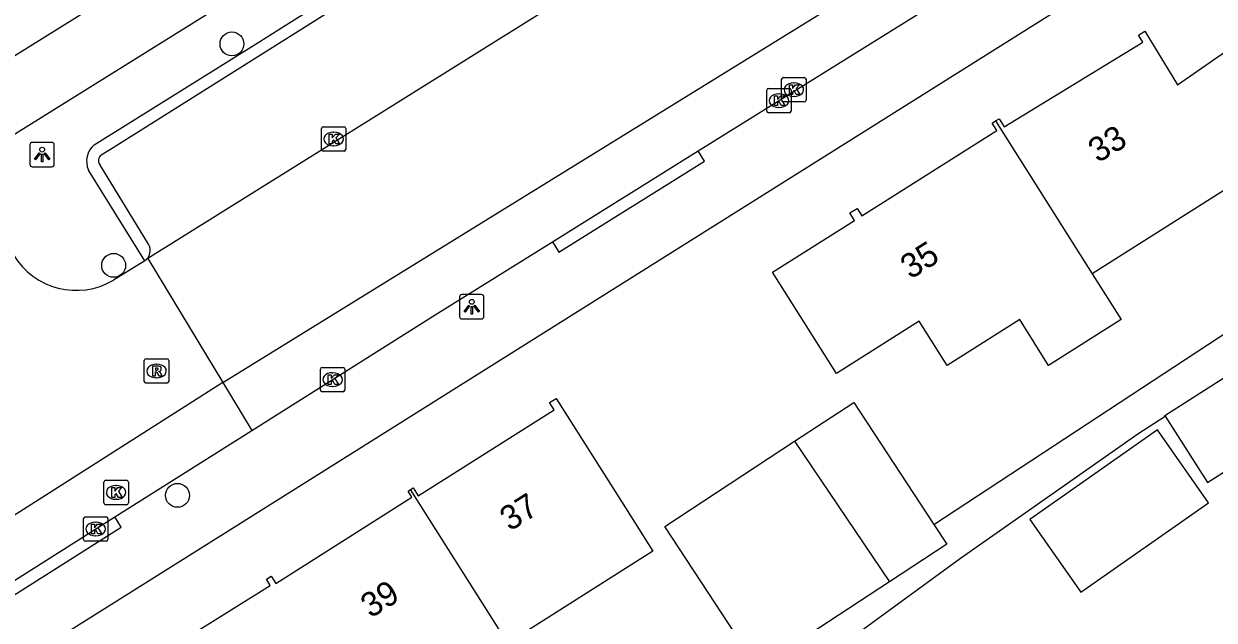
# Model space of a CAD drawing. Extents: x 159280 to 160375, y 384531 to 385872.
# Drawn here: x 159606.27 to 159655.03, y 385320.28 to 385344.69 of the extents above; entities that cross this region are included whole.
import ezdxf

# ---------------------------------------------------------------- set-up
doc = ezdxf.new("R2010")
doc.units = 0
for name, color, linetype in [('IMGEO_Boom', 7, 'Continuous'), ('IMGEO_Kolk', 7, 'Continuous'), ('IMGEO_Lichtpunt', 7, 'Continuous'), ('IMGEO_Pand', 7, 'Continuous'), ('IMGEO_Pand_nummerreeks', 7, 'Continuous'), ('IMGEO_Parkeervlak_open', 7, 'Continuous'), ('IMGEO_Rijbaan_lokaal_open', 7, 'Continuous'), ('IMGEO_Rioolput', 7, 'Continuous'), ('IMGEO_Voetpad_open', 7, 'Continuous')]:
    doc.layers.add(name, color=color, linetype=linetype)

msp = doc.modelspace()

# ---------------------------------------------------------------- linework, layer by layer
at = {"layer": 'IMGEO_Boom'}
for centre in [(159614.795, 385343.87), (159609.948, 385334.806), (159612.562, 385325.39)]:
    msp.add_circle(centre, 0.489, dxfattribs=at)
at = {"layer": 'IMGEO_Kolk'}
for p, q in [((159637.314, 385341.571), (159637.314, 385342.423)), ((159637.389, 385342.497), (159638.241, 385342.497)), ((159637.802, 385342.277), (159637.827, 385342.277)), ((159638.315, 385342.423), (159638.315, 385341.571)), ((159636.703, 385341.123), (159636.703, 385341.975)), ((159636.778, 385342.049), (159637.63, 385342.049)), ((159637.191, 385341.829), (159637.216, 385341.829)), ((159637.704, 385341.975), (159637.704, 385341.123)), ((159638.241, 385341.497), (159637.389, 385341.497)), ((159637.825, 385341.717), (159637.8, 385341.717)), ((159637.63, 385341.049), (159636.778, 385341.049)), ((159637.214, 385341.269), (159637.189, 385341.269)), ((159618.459, 385339.554), (159618.459, 385340.406)), ((159618.534, 385340.48), (159619.386, 385340.48)), ((159619.46, 385340.406), (159619.46, 385339.554)), ((159618.947, 385340.26), (159618.972, 385340.26)), ((159619.386, 385339.48), (159618.534, 385339.48)), ((159618.97, 385339.7), (159618.945, 385339.7)), ((159618.493, 385330.629), (159619.345, 385330.629)), ((159618.418, 385329.703), (159618.418, 385330.555)), ((159618.906, 385330.409), (159618.931, 385330.409)), ((159619.419, 385330.555), (159619.419, 385329.703)), ((159619.345, 385329.629), (159618.493, 385329.629)), ((159618.929, 385329.849), (159618.904, 385329.849)), ((159609.549, 385325.083), (159609.549, 385325.935)), ((159609.624, 385326.009), (159610.476, 385326.009)), ((159610.037, 385325.789), (159610.062, 385325.789)), ((159610.55, 385325.935), (159610.55, 385325.083)), ((159610.06, 385325.229), (159610.035, 385325.229)), ((159610.476, 385325.009), (159609.624, 385325.009)), ((159608.713, 385323.586), (159608.713, 385324.438)), ((159608.788, 385324.512), (159609.64, 385324.512)), ((159609.201, 385324.292), (159609.226, 385324.292)), ((159609.714, 385324.438), (159609.714, 385323.586)), ((159609.64, 385323.512), (159608.788, 385323.512)), ((159609.224, 385323.732), (159609.199, 385323.732))]:
    msp.add_line(p, q, dxfattribs=at)
for points in [[(159637.314, 385341.571), (159637.314, 385342.423)], [(159637.389, 385342.497), (159638.241, 385342.497)], [(159638.315, 385342.423), (159638.315, 385341.571)], [(159636.703, 385341.123), (159636.703, 385341.975)], [(159636.778, 385342.049), (159637.63, 385342.049)], [(159637.635, 385342.197), (159637.758, 385342.197), (159637.758, 385342.046), (159637.888, 385342.197), (159638.052, 385342.197), (159637.906, 385342.046), (159638.059, 385341.797), (159637.907, 385341.797), (159637.822, 385341.961), (159637.758, 385341.894), (159637.758, 385341.797), (159637.635, 385341.797), (159637.635, 385342.197)], [(159637.704, 385341.975), (159637.704, 385341.123)], [(159637.024, 385341.749), (159637.147, 385341.749), (159637.147, 385341.598), (159637.277, 385341.749), (159637.441, 385341.749), (159637.295, 385341.598), (159637.448, 385341.349), (159637.296, 385341.349), (159637.211, 385341.513), (159637.147, 385341.446), (159637.147, 385341.349), (159637.024, 385341.349), (159637.024, 385341.749)], [(159638.241, 385341.497), (159637.389, 385341.497)], [(159637.63, 385341.049), (159636.778, 385341.049)], [(159618.459, 385339.554), (159618.459, 385340.406)], [(159618.534, 385340.48), (159619.386, 385340.48)], [(159619.46, 385340.406), (159619.46, 385339.554)], [(159618.78, 385340.18), (159618.903, 385340.18), (159618.903, 385340.029), (159619.033, 385340.18), (159619.197, 385340.18), (159619.051, 385340.029), (159619.204, 385339.78), (159619.052, 385339.78), (159618.967, 385339.944), (159618.903, 385339.877), (159618.903, 385339.78), (159618.78, 385339.78), (159618.78, 385340.18)], [(159619.386, 385339.48), (159618.534, 385339.48)], [(159618.493, 385330.629), (159619.345, 385330.629)], [(159618.418, 385329.703), (159618.418, 385330.555)], [(159618.739, 385330.329), (159618.862, 385330.329), (159618.862, 385330.178), (159618.992, 385330.329), (159619.156, 385330.329), (159619.01, 385330.178), (159619.163, 385329.929), (159619.011, 385329.929), (159618.926, 385330.093), (159618.862, 385330.026), (159618.862, 385329.929), (159618.739, 385329.929), (159618.739, 385330.329)], [(159619.419, 385330.555), (159619.419, 385329.703)], [(159619.345, 385329.629), (159618.493, 385329.629)], [(159609.549, 385325.083), (159609.549, 385325.935)], [(159609.624, 385326.009), (159610.476, 385326.009)], [(159609.87, 385325.709), (159609.993, 385325.709), (159609.993, 385325.558), (159610.123, 385325.709), (159610.287, 385325.709), (159610.141, 385325.558), (159610.294, 385325.309), (159610.142, 385325.309), (159610.057, 385325.473), (159609.993, 385325.406), (159609.993, 385325.309), (159609.87, 385325.309), (159609.87, 385325.709)], [(159610.55, 385325.935), (159610.55, 385325.083)], [(159610.476, 385325.009), (159609.624, 385325.009)], [(159608.713, 385323.586), (159608.713, 385324.438)], [(159608.788, 385324.512), (159609.64, 385324.512)], [(159609.714, 385324.438), (159609.714, 385323.586)], [(159609.034, 385324.212), (159609.157, 385324.212), (159609.157, 385324.061), (159609.287, 385324.212), (159609.451, 385324.212), (159609.305, 385324.061), (159609.458, 385323.812), (159609.306, 385323.812), (159609.221, 385323.976), (159609.157, 385323.909), (159609.157, 385323.812), (159609.034, 385323.812), (159609.034, 385324.212)], [(159609.64, 385323.512), (159608.788, 385323.512)]]:
    msp.add_lwpolyline(points, dxfattribs=at)
for centre, start, end in [((159637.391, 385342.421), 91.552, 178.448), ((159637.391, 385342.421), 91.552, 178.448), ((159638.239, 385342.421), 1.552, 88.448), ((159638.239, 385342.421), 1.552, 88.448), ((159636.78, 385341.973), 91.552, 178.448), ((159636.78, 385341.973), 91.552, 178.448), ((159637.628, 385341.973), 1.552, 88.448), ((159637.628, 385341.973), 1.552, 88.448), ((159637.391, 385341.573), 181.552, 268.448), ((159637.391, 385341.573), 181.552, 268.448), ((159638.239, 385341.573), 271.552, 358.448), ((159638.239, 385341.573), 271.552, 358.448), ((159636.78, 385341.125), 181.552, 268.448), ((159636.78, 385341.125), 181.552, 268.448), ((159637.628, 385341.125), 271.552, 358.448), ((159637.628, 385341.125), 271.552, 358.448), ((159618.536, 385340.404), 91.552, 178.448), ((159618.536, 385340.404), 91.552, 178.448), ((159619.384, 385340.404), 1.552, 88.448), ((159619.384, 385340.404), 1.552, 88.448), ((159618.536, 385339.556), 181.552, 268.448), ((159618.536, 385339.556), 181.552, 268.448), ((159619.384, 385339.556), 271.552, 358.448), ((159619.384, 385339.556), 271.552, 358.448), ((159618.495, 385330.553), 91.552, 178.448), ((159618.495, 385330.553), 91.552, 178.448), ((159619.343, 385330.553), 1.552, 88.448), ((159619.343, 385330.553), 1.552, 88.448), ((159618.495, 385329.705), 181.552, 268.448), ((159618.495, 385329.705), 181.552, 268.448), ((159619.343, 385329.705), 271.552, 358.448), ((159619.343, 385329.705), 271.552, 358.448), ((159609.626, 385325.933), 91.552, 178.448), ((159609.626, 385325.933), 91.552, 178.448), ((159610.474, 385325.933), 1.552, 88.448), ((159610.474, 385325.933), 1.552, 88.448), ((159609.626, 385325.085), 181.552, 268.448), ((159609.626, 385325.085), 181.552, 268.448), ((159610.474, 385325.085), 271.552, 358.448), ((159610.474, 385325.085), 271.552, 358.448), ((159608.79, 385324.436), 91.552, 178.448), ((159608.79, 385324.436), 91.552, 178.448), ((159609.638, 385324.436), 1.552, 88.448), ((159609.638, 385324.436), 1.552, 88.448), ((159608.79, 385323.588), 181.552, 268.448), ((159608.79, 385323.588), 181.552, 268.448), ((159609.638, 385323.588), 271.552, 358.448), ((159609.638, 385323.588), 271.552, 358.448)]:
    msp.add_arc(centre, 0.0765, start, end, dxfattribs=at)
for centre, major_axis, ratio, start_param, end_param in [((159637.801, 385341.997), (-0.387, 0.002), 0.722429, 4.712389, 7.853982), ((159637.826, 385341.997), (-0.39, 0.002), 0.717154, 1.570796, 4.712389), ((159637.19, 385341.549), (-0.387, 0.002), 0.722429, 4.712389, 7.853982), ((159637.215, 385341.549), (-0.39, 0.002), 0.717154, 1.570796, 4.712389), ((159618.946, 385339.98), (-0.387, 0.002), 0.722429, 4.712389, 7.853982), ((159618.971, 385339.98), (-0.39, 0.002), 0.717154, 1.570796, 4.712389), ((159618.905, 385330.129), (-0.387, 0.002), 0.722429, 4.712389, 7.853982), ((159618.93, 385330.129), (-0.39, 0.002), 0.717154, 1.570796, 4.712389), ((159610.036, 385325.509), (-0.387, 0.002), 0.722429, 4.712389, 7.853982), ((159610.061, 385325.509), (-0.39, 0.002), 0.717154, 1.570796, 4.712389), ((159609.2, 385324.012), (-0.387, 0.002), 0.722429, 4.712389, 7.853982), ((159609.225, 385324.012), (-0.39, 0.002), 0.717154, 1.570796, 4.712389)]:
    msp.add_ellipse(centre, major_axis=major_axis, ratio=ratio, start_param=start_param, end_param=end_param, dxfattribs=at)
at = {"layer": 'IMGEO_Lichtpunt'}
for p, q in [((159607.422, 385339.842), (159606.614, 385339.842)), ((159607.422, 385339.842), (159606.614, 385339.842)), ((159606.52, 385339.747), (159606.52, 385338.94)), ((159606.52, 385339.747), (159606.52, 385338.94)), ((159607.516, 385338.94), (159607.516, 385339.747)), ((159607.516, 385338.94), (159607.516, 385339.747)), ((159606.614, 385338.846), (159607.422, 385338.846)), ((159606.614, 385338.846), (159607.422, 385338.846)), ((159624.12, 385333.512), (159624.12, 385332.705)), ((159624.12, 385333.512), (159624.12, 385332.705)), ((159625.022, 385333.607), (159624.214, 385333.607)), ((159625.022, 385333.607), (159624.214, 385333.607)), ((159625.116, 385332.705), (159625.116, 385333.512)), ((159625.116, 385332.705), (159625.116, 385333.512)), ((159624.214, 385332.611), (159625.022, 385332.611)), ((159624.214, 385332.611), (159625.022, 385332.611))]:
    msp.add_line(p, q, dxfattribs=at)
for points in [[(159606.894, 385339.411), (159606.933, 385339.383), (159606.745, 385339.121), (159606.707, 385339.148), (159606.894, 385339.411)], [(159606.996, 385339.363), (159607.043, 385339.363), (159607.043, 385339.041), (159606.996, 385339.041), (159606.996, 385339.363)], [(159607.106, 385339.383), (159607.144, 385339.41), (159607.331, 385339.148), (159607.292, 385339.12), (159607.106, 385339.383)], [(159624.494, 385333.176), (159624.533, 385333.148), (159624.345, 385332.886), (159624.307, 385332.913), (159624.494, 385333.176)], [(159624.596, 385333.128), (159624.643, 385333.128), (159624.643, 385332.806), (159624.596, 385332.806), (159624.596, 385333.128)], [(159624.706, 385333.148), (159624.744, 385333.175), (159624.931, 385332.913), (159624.892, 385332.885), (159624.706, 385333.148)]]:
    msp.add_lwpolyline(points, dxfattribs=at)
for centre in [(159607.019, 385339.545), (159624.619, 385333.31)]:
    msp.add_circle(centre, 0.0994, dxfattribs=at)
for centre, start, end in [((159606.614, 385339.747), 90, 180), ((159606.614, 385339.747), 90, 180), ((159607.422, 385339.747), 0, 90), ((159607.422, 385339.747), 0, 90), ((159606.614, 385338.94), 180, 270), ((159606.614, 385338.94), 180, 270), ((159607.422, 385338.94), 270, 0), ((159607.422, 385338.94), 270, 360), ((159624.214, 385333.512), 90, 180), ((159624.214, 385333.512), 90, 180), ((159625.022, 385333.512), 0, 90), ((159625.022, 385333.512), 0, 90), ((159624.214, 385332.705), 180, 270), ((159624.214, 385332.705), 180, 270), ((159625.022, 385332.705), 270, 0), ((159625.022, 385332.705), 270, 360)]:
    msp.add_arc(centre, 0.0946, start, end, dxfattribs=at)
at = {"layer": 'IMGEO_Pand'}
for points in [[(159646.082, 385340.717), (159646.221, 385340.805), (159646.429, 385340.476), (159652.114, 385343.937), (159651.933, 385344.227), (159652.197, 385344.395), (159653.532, 385342.202), (159658.982, 385345.989)], [(159650.038, 385334.462), (159651.222, 385332.59), (159648.251, 385330.711), (159647.067, 385332.583), (159644.102, 385330.707), (159642.95, 385332.526), (159639.561, 385330.382), (159636.943, 385334.522), (159640.303, 385336.648), (159640.11, 385336.952), (159640.402, 385337.137), (159640.596, 385336.829), (159646.132, 385340.331), (159645.943, 385340.629), (159646.082, 385340.717)], [(159646.082, 385340.717), (159650.038, 385334.462)], [(159661.483, 385335.963), (159659.249, 385339.358), (159659.069, 385339.617), (159656.4, 385337.862), (159656.095, 385338.294), (159650.038, 385334.462)], [(159653.032, 385328.628), (159653.008, 385328.666), (159656.411, 385330.831), (159656.611, 385330.517)], [(159653.032, 385328.628), (159654.758, 385325.916), (159658.16, 385328.081), (159656.611, 385330.517)], [(159622.11, 385325.63), (159622.217, 385325.697), (159622.424, 385325.371), (159627.993, 385328.898), (159627.807, 385329.191), (159628.074, 385329.359), (159630.749, 385325.135), (159632.036, 385323.102), (159626.095, 385319.34)], [(159637.838, 385327.602), (159640.269, 385329.197), (159643.552, 385324.195)], [(159649.577, 385321.426), (159654.797, 385325.087), (159652.707, 385328.066), (159647.488, 385324.405), (159649.577, 385321.426)], [(159636.344, 385318.32), (159632.535, 385324.122), (159637.838, 385327.602)], [(159637.838, 385327.602), (159641.726, 385321.852)], [(159616.768, 385313.509), (159614.943, 385316.406), (159612.948, 385319.573), (159616.365, 385321.706), (159616.206, 385321.957), (159616.398, 385322.079), (159616.587, 385321.781), (159622.166, 385325.314), (159622.007, 385325.565), (159622.11, 385325.63)], [(159626.095, 385319.34), (159622.11, 385325.63)], [(159643.552, 385324.195), (159644.077, 385323.395), (159641.726, 385321.852)], [(159641.726, 385321.852), (159636.344, 385318.32)]]:
    msp.add_lwpolyline(points, dxfattribs=at)
at = {"layer": 'IMGEO_Parkeervlak_open'}
msp.add_lwpolyline([(159614.419, 385330.007), (159615.607, 385328.042)], dxfattribs=at)
at = {"layer": 'IMGEO_Rijbaan_lokaal_open'}
for points in [[(159614.419, 385330.007), (159640.215, 385345.938), (159644.265, 385348.476), (159693.538, 385379.269), (159694.578, 385379.919), (159695.635, 385378.201)], [(159627.402, 385345.101), (159618.688, 385339.659), (159611.352, 385335.08)], [(159611.219, 385334.995), (159609.941, 385334.203)], [(159611.352, 385335.08), (159611.219, 385334.995)], [(159611.352, 385335.08), (159614.419, 385330.007)], [(159614.419, 385330.007), (159588.255, 385313.356)]]:
    msp.add_lwpolyline(points, dxfattribs=at)
msp.add_arc((159608.412, 385336.771), 2.989, 210.8156, 300.7699, dxfattribs=at)
at = {"layer": 'IMGEO_Rioolput'}
for p, q in [((159611.204, 385330.056), (159611.204, 385330.908)), ((159611.279, 385330.982), (159612.131, 385330.982)), ((159611.692, 385330.762), (159611.717, 385330.762)), ((159612.205, 385330.908), (159612.205, 385330.056)), ((159611.715, 385330.202), (159611.69, 385330.202)), ((159612.131, 385329.982), (159611.279, 385329.982))]:
    msp.add_line(p, q, dxfattribs=at)
for points in [[(159611.204, 385330.056), (159611.204, 385330.908)], [(159611.279, 385330.982), (159612.131, 385330.982)], [(159611.793, 385330.68), (159611.541, 385330.682), (159611.541, 385330.282)], [(159611.719, 385330.601), (159611.665, 385330.601), (159611.665, 385330.52)], [(159612.205, 385330.908), (159612.205, 385330.056)], [(159611.541, 385330.282), (159611.665, 385330.282), (159611.665, 385330.444), (159611.676, 385330.444)], [(159611.665, 385330.52), (159611.717, 385330.52)], [(159611.723, 385330.415), (159611.794, 385330.282), (159611.934, 385330.282), (159611.869, 385330.408)], [(159612.131, 385329.982), (159611.279, 385329.982)]]:
    msp.add_lwpolyline(points, dxfattribs=at)
for centre, radius, start, end in [((159611.281, 385330.906), 0.0765, 91.552, 178.448), ((159611.281, 385330.906), 0.0765, 91.552, 178.448), ((159611.725, 385330.505), 0.0964, 77.0061, 93.1865), ((159611.739, 385330.562), 0.0378, 276.6634, 79.6772), ((159611.792, 385330.57), 0.109, 350.3612, 89.416), ((159612.129, 385330.906), 0.0765, 1.552, 88.448), ((159612.129, 385330.906), 0.0765, 1.552, 88.448), ((159611.675, 385330.391), 0.0533, 26.0293, 88.6989), ((159611.701, 385330.709), 0.19, 274.7715, 282.9687), ((159611.79, 385330.57), 0.112, 277.5842, 350.9817), ((159611.774, 385330.355), 0.108, 29.5134, 73.7905), ((159611.281, 385330.058), 0.0765, 181.552, 268.448), ((159611.281, 385330.058), 0.0765, 181.552, 268.448), ((159612.129, 385330.058), 0.0765, 271.552, 358.448), ((159612.129, 385330.058), 0.0765, 271.552, 358.448)]:
    msp.add_arc(centre, radius, start, end, dxfattribs=at)
for centre, major_axis, ratio, start_param, end_param in [((159611.691, 385330.482), (-0.387, 0.002), 0.722429, 4.712389, 7.853982), ((159611.716, 385330.482), (-0.39, 0.002), 0.717154, 1.570796, 4.712389)]:
    msp.add_ellipse(centre, major_axis=major_axis, ratio=ratio, start_param=start_param, end_param=end_param, dxfattribs=at)
at = {"layer": 'IMGEO_Voetpad_open'}
for points in [[(159603.631, 385338.78), (159624.51, 385351.792), (159628.319, 385345.666)], [(159633.896, 385339.491), (159641.334, 385344.123), (159645.375, 385346.64), (159647.218, 385347.788), (159651.347, 385350.386)], [(159656.241, 385350.023), (159653.846, 385348.536), (159590.968, 385309.084)], [(159609.152, 385339.74), (159615.941, 385343.971), (159617.237, 385344.788), (159624.021, 385349.029)], [(159609.442, 385339.325), (159609.823, 385339.569), (159624.284, 385348.67)], [(159609.689, 385347.581), (159608.873, 385347.054), (159609.696, 385345.751), (159603.097, 385341.65)], [(159627.92, 385335.769), (159633.896, 385339.491)], [(159627.92, 385335.769), (159628.184, 385335.345), (159634.16, 385339.067), (159633.896, 385339.491)], [(159611.379, 385335.677), (159609.38, 385338.929)], [(159611.219, 385334.995), (159608.92, 385338.708)], [(159643.552, 385324.195), (159661.483, 385335.963)], [(159615.607, 385328.042), (159623.113, 385332.775), (159627.92, 385335.769)], [(159629.381, 385311.962), (159634.6, 385315.587), (159637.457, 385317.576), (159644.639, 385322.813), (159651.911, 385327.914), (159653.032, 385328.628)], [(159609.996, 385324.505), (159615.607, 385328.042)], [(159604.422, 385320.992), (159609.996, 385324.505)], [(159604.422, 385320.992), (159604.688, 385320.57), (159610.262, 385324.083), (159609.996, 385324.505)]]:
    msp.add_lwpolyline(points, dxfattribs=at)
for centre, radius, start, end in [((159609.708, 385339.073), 0.869, 129.8298, 204.8305), ((159609.6, 385339.097), 0.277, 124.6969, 217.5065), ((159610.936, 385335.421), 0.511, 303.5566, 30.0373)]:
    msp.add_arc(centre, radius, start, end, dxfattribs=at)

# ---------------------------------------------------------------- texts
at = {"layer": 'IMGEO_Pand_nummerreeks'}
for s, rotation, p in [('33', 31.3351, (159650.272, 385338.976)), ('35', 32.2976, (159642.592, 385334.212)), ('37', 31.9629, (159626.178, 385323.898)), ('39', 31.9653, (159620.475, 385320.34))]:
    msp.add_text(s, height=1, rotation=rotation, dxfattribs=at).set_placement(p)

doc.saveas('drawing.dxf')
